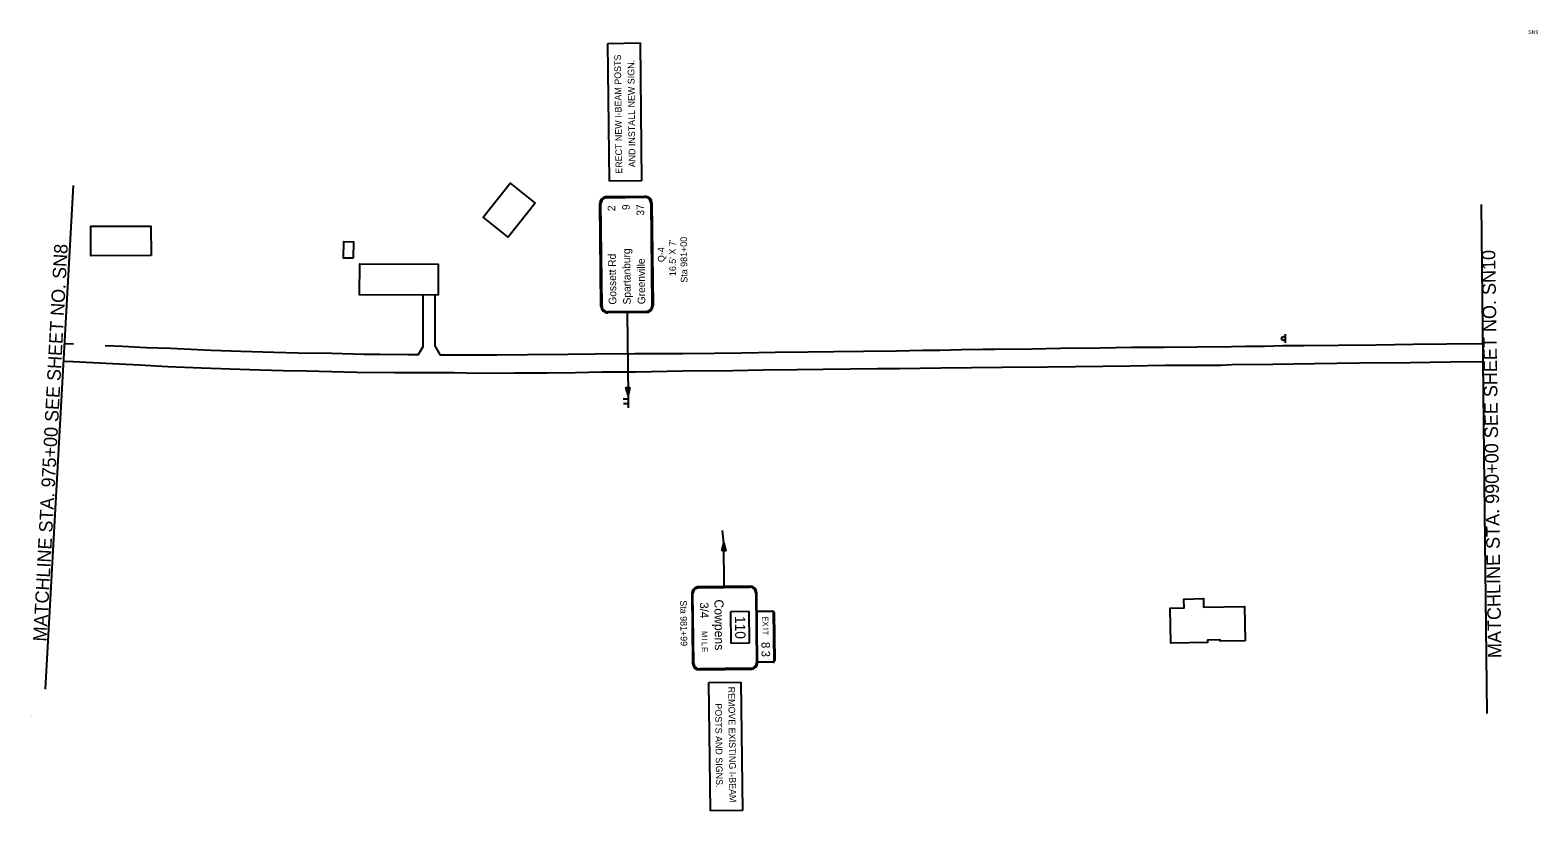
# Model space of a CAD drawing. Extents: x 1738744 to 1740330, y 1165669 to 1166490.
import ezdxf

# ---------------------------------------------------------------- set-up
doc = ezdxf.new("R2010")
doc.units = 0
for name, color, linetype in [('Default', 7, 'Continuous'), ('RD_EX_Bldg', 7, 'Continuous'), ('RD_EX_Driveway', 7, 'Continuous'), ('RD_EX_Road', 7, 'Continuous'), ('RD_SHT_MatchLine', 7, 'Continuous'), ('RD_SHT_TX', 7, 'Continuous'), ('SN_P_Signs', 7, 'Continuous')]:
    doc.layers.add(name, color=color, linetype=linetype)

msp = doc.modelspace()

# ---------------------------------------------------------------- linework, layer by layer
at = {"layer": 'RD_EX_Bldg'}
for points in [[(1739275.1, 1166308.3), (1739246.6, 1166272.4), (1739220.2, 1166293.4), (1739248.6, 1166329.3), (1739275.1, 1166308.3)], [(1738870.9, 1166253), (1738807.6, 1166252.7), (1738807.5, 1166283.8), (1738870.8, 1166284.1), (1738870.9, 1166253)], [(1739083.7, 1166250.3), (1739073.5, 1166250.4), (1739073.7, 1166267.7), (1739083.9, 1166267.6), (1739083.7, 1166250.3)], [(1739173, 1166211.4), (1739090.3, 1166211.8), (1739090.5, 1166244.4), (1739173.1, 1166244), (1739173, 1166211.4)], [(1740022, 1165848), (1739995.5, 1165847.5), (1739995.5, 1165848.9), (1739982.2, 1165848.7), (1739982.2, 1165846.2), (1739943.7, 1165845.5), (1739943, 1165882.4), (1739957.7, 1165882.7), (1739957.5, 1165891.9), (1739978, 1165892.3), (1739978.1, 1165883.4), (1740021.3, 1165884.2), (1740022, 1165848)]]:
    msp.add_lwpolyline(points, dxfattribs=at)
at = {"layer": 'RD_EX_Driveway'}
for points in [[(1739151.8, 1166148.6), (1739151.8, 1166148.6), (1739157, 1166157.6), (1739157.3, 1166186.2), (1739157.1, 1166199.6), (1739157.1, 1166202.7), (1739157, 1166211.5)], [(1739169.4, 1166211.4), (1739169.4, 1166190.5), (1739169.4, 1166158), (1739174.9, 1166148.4)]]:
    msp.add_lwpolyline(points, dxfattribs=at)
at = {"layer": 'RD_EX_Road'}
for points in [[(1738789.4, 1166159.9), (1738780.2, 1166160.3)], [(1739151.9, 1166148.6), (1739151.8, 1166148.6), (1739141, 1166148.6), (1739112.1, 1166148.9), (1739095.1, 1166149), (1739061.2, 1166150), (1739025.8, 1166150.6), (1739000, 1166151.3), (1738965.2, 1166152.3), (1738934, 1166153.3), (1738912.6, 1166154.2), (1738891.2, 1166155.2), (1738865.9, 1166156), (1738840.9, 1166157.3), (1738822.8, 1166158.3)], [(1740272.1, 1166160.2), (1740233.7, 1166159.9), (1740198.3, 1166159.4), (1740159.6, 1166158.9), (1740120.1, 1166158.4), (1740084.1, 1166158.2), (1740061.9, 1166158), (1740042.3, 1166157.6), (1740022.5, 1166157.6), (1740007.5, 1166157.1), (1739970.9, 1166156.9), (1739936.6, 1166156.4), (1739902.4, 1166156.3), (1739868.9, 1166155.7), (1739827.7, 1166155.2), (1739797.6, 1166154.7), (1739758.7, 1166154.3), (1739745.9, 1166154.2), (1739723.4, 1166154), (1739700.6, 1166153.4), (1739697.8, 1166153.4), (1739682.5, 1166153.2), (1739655.1, 1166152.6), (1739620.5, 1166152.3), (1739589.3, 1166151.9), (1739562.1, 1166151.6), (1739527.6, 1166151.1), (1739492.1, 1166150.5), (1739463.8, 1166150.2), (1739430.2, 1166149.8), (1739380.1, 1166149.6), (1739338.2, 1166149.4), (1739309.8, 1166149.1), (1739266.9, 1166148.7), (1739234.8, 1166148.3), (1739207.3, 1166148.4), (1739185.2, 1166148.3), (1739174.9, 1166148.4)], [(1740272.3, 1166141.2), (1740237.4, 1166140.8), (1740195.4, 1166140.4), (1740142.1, 1166139.9), (1740094.3, 1166139.1), (1740051, 1166138.6), (1740008, 1166138.1), (1739996.4, 1166137.5), (1739969.4, 1166137.5), (1739937.5, 1166137.4), (1739900.6, 1166136.9), (1739872.2, 1166136.3), (1739843.3, 1166136), (1739813.9, 1166135.8), (1739766.1, 1166135.2), (1739701.6, 1166134.5), (1739658.3, 1166134.1), (1739635.1, 1166134), (1739606.6, 1166133.7), (1739578.1, 1166133.2), (1739550.4, 1166132.8), (1739514.9, 1166132.4), (1739483, 1166132), (1739429.8, 1166131.4), (1739381.3, 1166130.5), (1739345.1, 1166130.3), (1739317.5, 1166129.9), (1739287.5, 1166129.3), (1739253.2, 1166129.3), (1739214.5, 1166129.1), (1739189.8, 1166129.7), (1739160.7, 1166129.6), (1739126.9, 1166129.8), (1739087.5, 1166130.1), (1739034.3, 1166131.4), (1739009.8, 1166131.7), (1738985.3, 1166132.4), (1738964.2, 1166133.4), (1738924, 1166134.7), (1738888.7, 1166136.2), (1738858.7, 1166137.7), (1738830.2, 1166139.2), (1738789, 1166141.2), (1738779.5, 1166141.8), (1738779.2, 1166141.8)]]:
    msp.add_lwpolyline(points, dxfattribs=at)
at = {"layer": 'RD_SHT_MatchLine'}
for points in [[(1738760, 1165797), (1738773.7, 1166044), (1738789.5, 1166326.7)], [(1740276.6, 1165771.7), (1740273.4, 1166044), (1740270.4, 1166306.8)]]:
    msp.add_lwpolyline(points, dxfattribs=at)
at = {"layer": 'SN_P_Signs'}
for p, q in [((1739351.6, 1166476.2), (1739385.3, 1166476.6)), ((1739353.3, 1166331.2), (1739351.6, 1166476.2)), ((1739385.3, 1166476.6), (1739386.9, 1166331.6)), ((1739386.9, 1166331.6), (1739353.3, 1166331.2)), ((1739344.2, 1166199.8), (1739343, 1166307.8)), ((1739345.4, 1166199.8), (1739344.2, 1166307.8)), ((1739371.7, 1166192.9), (1739372.7, 1166106.1)), ((1740064.3, 1166161.4), (1740064.2, 1166170.4)), ((1739372.7, 1166102.2), (1739367.7, 1166102.2)), ((1739372.8, 1166097.2), (1739367.8, 1166097.1)), ((1739372.7, 1166106.1), (1739372.8, 1166093.1)), ((1739473.4, 1165950.8), (1739472, 1165964)), ((1739473.9, 1165905.2), (1739473.4, 1165950.8)), ((1739457.8, 1165804.2), (1739491.4, 1165804.6)), ((1739459.4, 1165669.2), (1739457.8, 1165804.2)), ((1739491.4, 1165804.6), (1739493, 1165669.6)), ((1739493, 1165669.6), (1739459.4, 1165669.2))]:
    msp.add_line(p, q, dxfattribs=at)
for points in [[(1739350.1, 1166315), (1739390.5, 1166315.5)], [(1739350.1, 1166313.8), (1739390.5, 1166314.3)], [(1739396.6, 1166308.4), (1739397.8, 1166200.4)], [(1739397.8, 1166308.4), (1739399, 1166200.4)], [(1739391.9, 1166194.3), (1739351.5, 1166193.9)], [(1739391.9, 1166193.1), (1739351.5, 1166192.7)], [(1739500.9, 1165905.5), (1739446.9, 1165904.8)], [(1739446.9, 1165903.6), (1739500.9, 1165904.3)], [(1739439.8, 1165897.6), (1739440.6, 1165824.5)], [(1739441.8, 1165824.5), (1739441, 1165897.6)], [(1739507, 1165898.3), (1739507.8, 1165825.2)], [(1739509, 1165825.2), (1739508.2, 1165898.3)], [(1739500, 1165878.8), (1739480.3, 1165878.6)], [(1739480.3, 1165878.6), (1739480.7, 1165845.5)], [(1739500.4, 1165845.7), (1739500, 1165878.8)], [(1739524.6, 1165878.8), (1739508.4, 1165878.6), (1739508.4, 1165879.2), (1739524.6, 1165879.4)], [(1739526.4, 1165827.2), (1739525.8, 1165877.6)], [(1739526.4, 1165877.6), (1739527, 1165827.2)], [(1739480.7, 1165845.5), (1739500.4, 1165845.7)], [(1739509, 1165825.8), (1739525.2, 1165826)], [(1739525.2, 1165825.4), (1739509, 1165825.2), (1739509, 1165825.8)], [(1739501.9, 1165819.2), (1739447.9, 1165818.5)], [(1739447.9, 1165817.3), (1739501.9, 1165818)]]:
    msp.add_lwpolyline(points, dxfattribs=at)
for points in [[(1739374.6, 1166114.3), (1739372.7, 1166106.1), (1739370.5, 1166114.3)], [(1739471.4, 1165942.6), (1739473.4, 1165950.8), (1739475.5, 1165942.7)]]:
    msp.add_lwpolyline(points, close=True, dxfattribs=at)
msp.add_circle((1740062.2, 1166165.9), 2, dxfattribs=at)
for centre, radius, start, end in [((1739350.2, 1166307.8), 7.2, 90.6542, 180.6542), ((1739350.2, 1166307.8), 6, 90.6542, 180.6542), ((1739390.6, 1166308.3), 7.2, 0.6542, 90.6542), ((1739390.6, 1166308.3), 6, 0.6542, 90.6542), ((1739351.4, 1166199.9), 7.2, 180.6542, 270.6542), ((1739351.4, 1166199.9), 6, 180.6542, 270.6542), ((1739391.8, 1166200.3), 6, 270.6542, 0.6542), ((1739391.8, 1166200.3), 7.2, 270.6542, 0.6542), ((1739447, 1165897.6), 7.2, 90.6543, 180.6543), ((1739447, 1165897.6), 6, 90.6543, 180.6543), ((1739501, 1165898.3), 7.2, 0.6543, 90.6543), ((1739501, 1165898.3), 6, 0.6543, 90.6543), ((1739524.6, 1165877.6), 1.8, 0.6543, 90.6543), ((1739524.6, 1165877.6), 1.2, 0.6543, 90.6543), ((1739447.8, 1165824.5), 7.2, 180.6543, 270.6543), ((1739447.8, 1165824.5), 6, 180.6543, 270.6543), ((1739501.8, 1165825.2), 6, 270.6543, 0.6543), ((1739501.8, 1165825.2), 7.2, 270.6543, 0.6543), ((1739525.2, 1165827.2), 1.8, 270.6543, 0.6543), ((1739525.2, 1165827.2), 1.2, 270.6543, 0.6543)]:
    msp.add_arc(centre, radius, start, end, dxfattribs=at)

# ---------------------------------------------------------------- texts
at = {"layer": 'Default'}
for s, p in [('Sheet: 9', (1738743.7, 1165768.8)), ('Angle:  25.2910', (1738743.7, 1165768.6)), ('Align: A_I85', (1738743.7, 1165768.3))]:
    msp.add_text(s, height=0.208, dxfattribs=at).set_placement(p)
at = {"layer": 'RD_SHT_TX'}
msp.add_text('SN9', height=4, dxfattribs=at).set_placement((1740319.6, 1166486))
for s, rotation, p in [('MATCHLINE STA. 975+00 SEE SHEET NO. SN8', 86.9265, (1738760.9, 1165846.9)), ('MATCHLINE STA. 990+00 SEE SHEET NO. SN10', 90.8815, (1740291.5, 1165829.9))]:
    msp.add_text(s, height=14.173, rotation=rotation, dxfattribs=at).set_placement(p)
at = {"layer": 'SN_P_Signs'}
for s, height, rotation, p in [('ERECT NEW I-BEAM POSTS', 7, 90.6543, (1739366.6, 1166339.1)), ('AND INSTALL NEW SIGN.', 7, 90.6543, (1739380.5, 1166345.9)), ('2', 8, 90.6542, (1739359.3, 1166299.8)), ('9', 8, 90.6542, (1739374.5, 1166301)), ('37', 8, 90.6542, (1739389.7, 1166295)), ("16.5' X 7'", 7, 90.6543, (1739423.2, 1166231.5)), ('Sta 981+00', 7, 90.6543, (1739435.2, 1166224.6)), ('Gossett Rd', 8, 90.6542, (1739360.4, 1166201.5)), ('Spartanburg', 8, 90.6542, (1739375.6, 1166201.7)), ('Q-4', 7, 90.6543, (1739411.1, 1166246.2)), ('Greenville', 8, 90.6542, (1739390.8, 1166201.9)), ('Sta 981+99', 7, 270.6543, (1739427.5, 1165890.5)), ('3/4', 9, 270.6543, (1739448.3, 1165888.4)), ('Cowpens', 9.6, 270.6543, (1739463.5, 1165891.4)), ('110', 10.8, 270.6543, (1739485.2, 1165874)), ('E', 6, 270.6543, (1739514.1, 1165873.6)), ('M', 6, 270.6543, (1739450.1, 1165858.2)), ('X', 6, 270.6543, (1739514.2, 1165868.4)), ('I', 6, 270.6543, (1739514.3, 1165861.6)), ('T', 6, 270.6543, (1739514.3, 1165858.6)), ('I', 6, 270.6543, (1739450.2, 1165850.3)), ('L', 6, 270.6543, (1739450.2, 1165846.7)), ('E', 6, 270.6543, (1739450.3, 1165841.3)), ('8', 9, 270.6543, (1739513, 1165846.7)), ('3', 9, 270.6543, (1739513.1, 1165837.6)), ('REMOVE EXISTING I-BEAM', 7, 270.6543, (1739478.1, 1165799.7)), ('POSTS AND SIGNS.', 7, 270.6543, (1739464.3, 1165782.1))]:
    msp.add_text(s, height=height, rotation=rotation, dxfattribs=at).set_placement(p)

doc.saveas('drawing.dxf')
